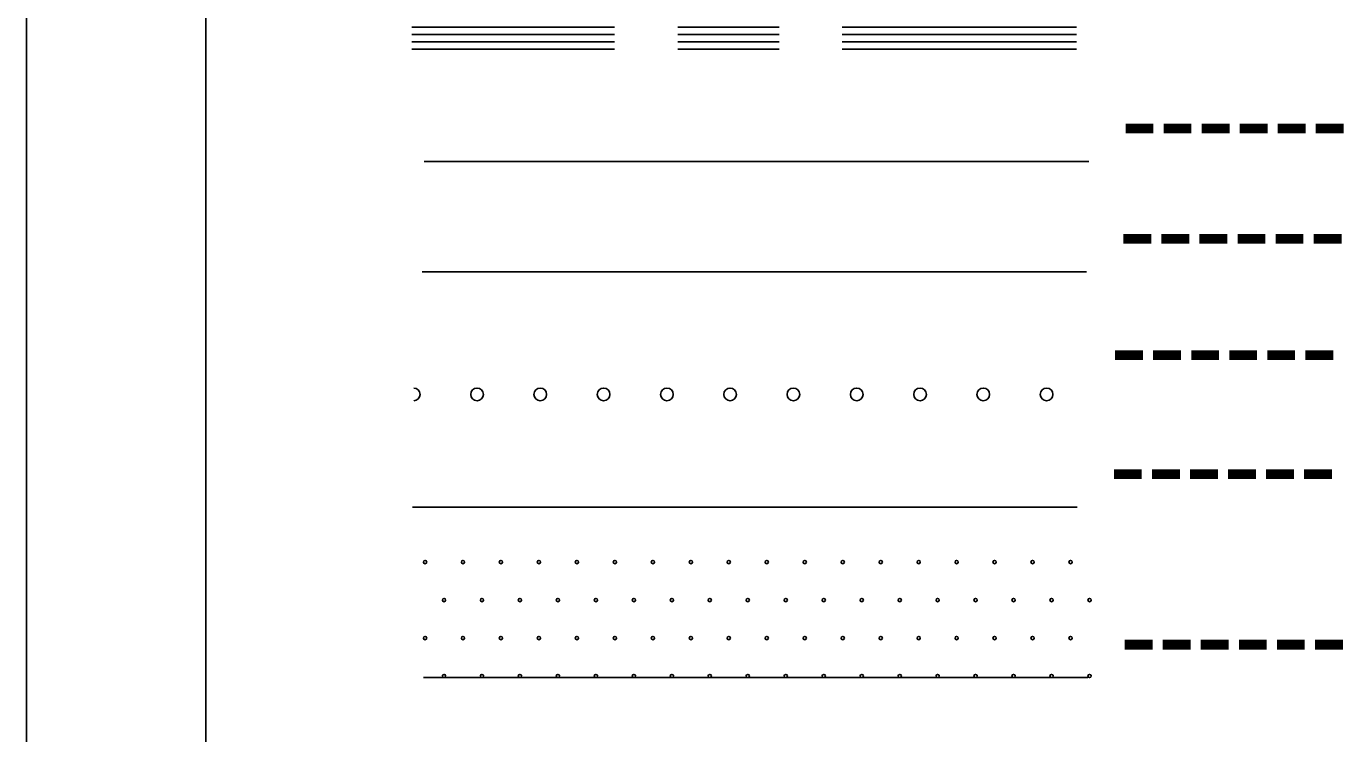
# Model space of a CAD drawing. Extents: x 408847 to 817539, y 923858 to 1151780.
# Drawn here: x 773223 to 779467, y 1009720 to 1013074 of the extents above; entities that cross this region are included whole.
import ezdxf

# ---------------------------------------------------------------- set-up
doc = ezdxf.new("R2010")
doc.units = 0
doc.layers.add('Quad Borders', color=7, linetype='Continuous')

msp = doc.modelspace()

# ---------------------------------------------------------------- linework, layer by layer
at = {"layer": 'Quad Borders'}
for p, q in [((773222.5, 996643.4), (773222.6, 1049600.6)), ((774072.5, 997493.4), (774072.6, 1048750.6)), ((775108.2, 1012434), (778258.2, 1012434)), ((775098.1, 1011910.1), (778248.1, 1011910.1)), ((775053.2, 1010794.5), (778203.2, 1010794.5)), ((775104.5, 1009985.7), (778254.5, 1009985.7))]:
    msp.add_line(p, q, dxfattribs=at)
for points in [[(775050.4, 1013069.9), (776010.4, 1013069.9)], [(776310.4, 1013069.9), (776790.4, 1013069.9)], [(777090.4, 1013069.9), (778200.4, 1013069.9)], [(775050.4, 1013035.1), (776010.4, 1013035.1)], [(775050.4, 1013000.3), (776010.4, 1013000.3)], [(776310.4, 1013035.1), (776790.4, 1013035.1)], [(776310.4, 1013000.3), (776790.4, 1013000.3)], [(777090.4, 1013035.1), (778200.4, 1013035.1)], [(777090.4, 1013000.3), (777990.4, 1013000.3)], [(777990.4, 1013000.3), (778200.4, 1013000.3)], [(775050.4, 1012965.5), (776010.4, 1012965.5)], [(776310.4, 1012965.5), (776790.4, 1012965.5)], [(777090.4, 1012965.5), (777990.4, 1012965.5)], [(777990.4, 1012965.5), (778200.4, 1012965.5)]]:
    msp.add_lwpolyline(points, dxfattribs=at)
for centre, radius in [((775358.7, 1011328.7), 30), ((775958.7, 1011328.7), 30), ((776558.7, 1011328.7), 30), ((777158.7, 1011328.7), 30), ((777758.7, 1011328.7), 30), ((775112.3, 1010533.5), 7.8), ((775292.3, 1010533.5), 7.8), ((775472.3, 1010533.5), 7.8), ((775652.3, 1010533.5), 7.8), ((775832.3, 1010533.5), 7.8), ((776012.3, 1010533.5), 7.8), ((776192.3, 1010533.5), 7.8), ((776372.3, 1010533.5), 7.8), ((776552.3, 1010533.5), 7.8), ((776732.3, 1010533.5), 7.8), ((776912.3, 1010533.5), 7.8), ((777092.3, 1010533.5), 7.8), ((777272.3, 1010533.5), 7.8), ((777452.3, 1010533.5), 7.8), ((777632.3, 1010533.5), 7.8), ((777812.3, 1010533.5), 7.8), ((777992.3, 1010533.5), 7.8), ((778172.3, 1010533.5), 7.8), ((775202.3, 1010353.5), 7.8), ((775382.3, 1010353.5), 7.8), ((775562.3, 1010353.5), 7.8), ((775742.3, 1010353.5), 7.8), ((775922.3, 1010353.5), 7.8), ((776102.3, 1010353.5), 7.8), ((776282.3, 1010353.5), 7.8), ((776462.3, 1010353.5), 7.8), ((776642.3, 1010353.5), 7.8), ((776822.3, 1010353.5), 7.8), ((777002.3, 1010353.5), 7.8), ((777182.3, 1010353.5), 7.8), ((777362.3, 1010353.5), 7.8), ((777542.3, 1010353.5), 7.8), ((777722.3, 1010353.5), 7.8), ((777902.3, 1010353.5), 7.8), ((778082.3, 1010353.5), 7.8), ((778262.3, 1010353.5), 7.8), ((775112.3, 1010173.5), 7.8), ((775292.3, 1010173.5), 7.8), ((775472.3, 1010173.5), 7.8), ((775652.3, 1010173.5), 7.8), ((775832.3, 1010173.5), 7.8), ((776012.3, 1010173.5), 7.8), ((776192.3, 1010173.5), 7.8), ((776372.3, 1010173.5), 7.8), ((776552.3, 1010173.5), 7.8), ((776732.3, 1010173.5), 7.8), ((776912.3, 1010173.5), 7.8), ((777092.3, 1010173.5), 7.8), ((777272.3, 1010173.5), 7.8), ((777452.3, 1010173.5), 7.8), ((777632.3, 1010173.5), 7.8), ((777812.3, 1010173.5), 7.8), ((777992.3, 1010173.5), 7.8), ((778172.3, 1010173.5), 7.8), ((775202.3, 1009993.5), 7.8), ((775382.3, 1009993.5), 7.8), ((775562.3, 1009993.5), 7.8), ((775742.3, 1009993.5), 7.8), ((775922.3, 1009993.5), 7.8), ((776102.3, 1009993.5), 7.8), ((776282.3, 1009993.5), 7.8), ((776462.3, 1009993.5), 7.8), ((776642.3, 1009993.5), 7.8), ((776822.3, 1009993.5), 7.8), ((777002.3, 1009993.5), 7.8), ((777182.3, 1009993.5), 7.8), ((777362.3, 1009993.5), 7.8), ((777542.3, 1009993.5), 7.8), ((777722.3, 1009993.5), 7.8), ((777902.3, 1009993.5), 7.8), ((778082.3, 1009993.5), 7.8), ((778262.3, 1009993.5), 7.8)]:
    msp.add_circle(centre, radius, dxfattribs=at)
for centre, start, end in [((775058.7, 1011328.7), 269.99991, 89.99991), ((775658.7, 1011328.7), 89.99991, 269.99991), ((775658.7, 1011328.7), 269.99991, 89.99991), ((776258.7, 1011328.7), 89.99991, 269.99991), ((776258.7, 1011328.7), 269.99991, 89.99991), ((776858.7, 1011328.7), 89.99991, 269.99991), ((776858.7, 1011328.7), 269.99991, 89.99991), ((777458.7, 1011328.7), 89.99991, 269.99991), ((777458.7, 1011328.7), 269.99991, 89.99991), ((778058.7, 1011328.7), 89.99991, 269.99991), ((778058.7, 1011328.7), 269.99991, 89.99991)]:
    msp.add_arc(centre, 30, start, end, dxfattribs=at)

# ---------------------------------------------------------------- texts
for rotation, p in [(359.99991, (778258.2, 1012434)), (359.99991, (778248.1, 1011910.1)), (359.99991, (778208.7, 1011358.7)), (359.99991, (778203.2, 1010794.5)), (359.9999, (778254.5, 1009985.7))]:
    msp.add_text(' ------', height=405, rotation=rotation, dxfattribs=at).set_placement(p)

doc.saveas('drawing.dxf')
